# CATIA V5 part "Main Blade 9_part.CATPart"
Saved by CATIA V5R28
Part number: Main Blade 9_part
Definition: design
Nomenclature: Main Blade 9_part
Source: Unknown
Bounding box of the stored display mesh (mm): x -8.631 to 3.781, y -5.936 to -1.689, z 1.529 to 7.748
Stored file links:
  D:\paraturbo-cad\STEP\Turbocompressor_for_Christophe\Main Blade 9_part.CATPart
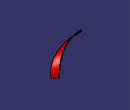
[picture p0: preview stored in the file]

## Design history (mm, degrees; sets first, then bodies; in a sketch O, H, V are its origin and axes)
Body1 "MANIFOLD_SOLID_BREP #56720" (main body)
  Solid1: solid without history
